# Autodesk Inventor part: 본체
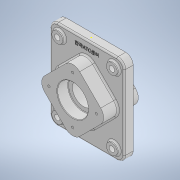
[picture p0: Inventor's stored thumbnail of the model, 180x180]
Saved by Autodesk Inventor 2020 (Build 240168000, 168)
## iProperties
Created: 2021-07
Part Number: 본체
Material: 일반
Document SubType Name: Modeling
Designer: Owner
Mass: 806.566 g
Surface Area: 962.824 cm^2
Volume: 806.566 cm^3
Density: 1 g/cm^3
Appearance: 기본값
Author: Owner
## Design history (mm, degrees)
sketch "스케치1"
  geometry: L1 (-75, -90)-(75, -90); L2 (75, -90)-(75, 90); L3 (75, 90)-(-75, 90); L4 (-75, 90)-(-75, -90); L5 (-75, -90)-(75, 90); L6 (75, -90)-(-75, 90); 1 further point
  constraints: 12 end point, 2 midpoint, 2 parallel, 1 horizontal, 1 perpendicular
  dimensions: "d0" = 150 distance of L3.end L2.end; "d1" = 180 distance of L2.end L1.end
extrude "돌출1" new body sketch "스케치1" stored distance "d2" = 18; taper "d3" = 0 deg
sketch "스케치2"
  geometry: L1 (0, -70.711)-(70.711, 0); L2 (70.711, 0)-(0, 70.711); L3 (0, 70.711)-(-70.711, 0); L4 (-70.711, 0)-(0, -70.711); L5 (0, -70.711)-(0, 70.711); L6 (70.711, 0)-(-70.711, 0); 4 further points
  constraints: 12 end point, 4 midpoint, 2 parallel, 1 coincident, 1 perpendicular, 1 vertical alignment
  dimensions: "d4" = 100 distance of L2.end L3.end; "d5" = 100 distance of L1.end L2.end
extrude "돌출2" join sketch "스케치2" distance "d6" = 29; taper "d7" = 0 deg
sketch "스케치3"
  geometry: L1 (0, 38)-(0, -35); L2 (31, 16)-(22.5, 16); L3 (70.711, -9)-(0, -9) reference; L4 (22.5, 16)-(22.5, -13); L5 (22.5, -13)-(31, -13); L6 (31, -13)-(31, -35); L7 (70.711, -35)-(0, -35) reference; L8 (31, 16)-(31, 38); L9 (70.711, 38)-(0, 38) reference; L10 (0, 9)-(0, 38) reference; L11 (31, 38)-(0, 38); L12 (0, -35)-(-70.711, -35) reference; L13 (31, -35)-(0, -35); 2 further points
  constraints: 16 end point, 3 perpendicular, 3 point on line, 3 vertical, 1 coincident, 1 collinear
  dimensions: "d10" = 22 distance of L5.end L6.end; "d11" = 22 distance of L2.start L8.end; "d12" = 62 diameter of L8 L1; "d13" = 62 diameter of L6 L1; "d16" = 45 diameter of L4 L1; "d17" = 8.5 distance of L2.start L2.end
revolve "회전1" sketch "스케치3" stored, may be unused: angle "d18" = 90 deg
sketch "스케치4" dims "d30" = 10
  geometry: L1 (-75, 90)-(-75, -90) reference; L2 (75, -90)-(75, 90) reference; L3 (75, 90)-(-75, 90) reference; C1 r 11 at (-55, 70); C2 r 11 at (55, 70); C3 r 11 at (-55, -70); C4 r 11 at (55, -70); 1 further point
  constraints: 4 centre point, 1 vertical, 4 other
  dimensions: "d19" = 22 diameter of C1; "d20" = 22 diameter of C2; "d21" = 110 distance of C2.centre C1.centre; "d22" = 20 distance from line of L1 C1.centre; "d23" = 20 distance from line of L2 C2.centre; "d24" = 20 distance from line of L3 C1.centre; "d27" = 140 distance of C1.centre C3.centre
extrude "돌출3" join sketch "스케치4" distance "d32" = 5; taper "d33" = 0 deg
sketch "스케치5"
  geometry: C1 r 11 at (0, 0) reference; C2 r 11 at (110, 0) reference; C3 r 11 at (110, -140) reference; C4 r 11 at (0, -140) reference; 5 further points
  constraints: 4 coincident
hole "구멍1" sketch "스케치5" at (0, 0), (110, 0), (110, -140), (0, -140) diameter "d34" = 11; stored, may be unused: countersink angle "d38" = 90 deg, drill point angle "d40" = 0 deg; dims "d35" = 8, "d36" = 4, "d37" = 2, "d39" = 30
fillet "모깎기1" dims "d41" = 20
fillet "모깎기2" dims "d42" = 3
fillet "모깎기3" dims "d43" = 15
fillet "모깎기4" dims "d44" = 3
fillet "모깎기5" dims "d45" = 3
sketch "스케치6"
  geometry: L1 (60, 90)-(-60, 90) reference; 2 further points
  constraints: 1 vertical alignment, 1 other
  dimensions: "d46" = 15 distance from line of point (0, 75) L1
feature "엠보싱1" sketch "스케치6" dims "d0" = 150, "d1" = 180, "d47" = 0.6, "d48" = 0
sketch "스케치7"
  geometry: 2 further points
  constraints: 1 vertical alignment
  dimensions: "d49" = 48 distance of point (0, 0) point (0, 48)
hole "구멍2" sketch "스케치7" at (0, 48) diameter "d50" = 4.917; stored, may be unused: countersink angle "d54" = 90 deg, drill point angle "d56" = 118 deg; dims "d51" = 10, "d52" = 4, "d53" = 2, "d55" = 13
fillet "모깎기8" dims "d62" = 1
chamfer "모따기1" distance "d63" = 1; stored, may be unused: second distance "d64" = 2, angle "d65" = 45 deg
sketch "스케치8"
  geometry: L1 (0, -70.711)-(70.711, 0); L2 (70.711, 0)-(0, 70.711); L3 (0, 70.711)-(-70.711, 0); L4 (-70.711, 0)-(0, -70.711); L5 (0, -70.711)-(0, 70.711); L6 (70.711, 0)-(-70.711, 0); 4 further points
  constraints: 12 end point, 4 midpoint, 2 parallel, 1 coincident, 1 horizontal alignment, 1 perpendicular, 1 vertical alignment
  dimensions: "d66" = 100 distance of L3.end L1.start
extrude "돌출4" join sketch "스케치8" distance "d67" = 23; taper "d68" = 0 deg
fillet "모깎기9" dims "d69" = 20
sketch "스케치9"
  geometry: 1 further point
sketch "스케치10"
  geometry: 2 further points
  constraints: 1 vertical alignment
  dimensions: "d70" = 48 distance of point (0, 0) point (0, 48)
hole "구멍3" sketch "스케치10" at (0, 48) diameter "d71" = 4.917; stored, may be unused: countersink angle "d75" = 90 deg, drill point angle "d77" = 118 deg; dims "d72" = 10, "d73" = 4, "d74" = 2, "d76" = 13
sketch "스케치11"
  geometry: C1 r 22.5 at (0, 0) reference; C2 r 31 at (0, 0); 1 further point
  constraints: 1 centre point, 1 coincident
  dimensions: "d78" = 62 diameter of C2
extrude "돌출5" cut sketch "스케치11" distance "d79" = 23; taper "d80" = 0 deg
fillet "모깎기10" dims "d81" = 1
chamfer "모따기2" distance "d82" = 1; stored, may be unused: second distance "d83" = 2, angle "d84" = 45 deg
fillet "모깎기11" dims "d88" = 3
node "솔리드1"
pattern_circular "원형 패턴1" dims angle "d58" = 360 deg
mirror "미러2"
pattern_circular "원형 패턴2" dims angle "d86" = 360 deg
feature "A9D066F2-1C7D-4E18-AEED-F7BC21143FA4" dims "d34" = 11, "d35" = 8, "d36" = 4, "d37" = 2, "d38" = 90 deg, "d39" = 30, "d40" = 0
